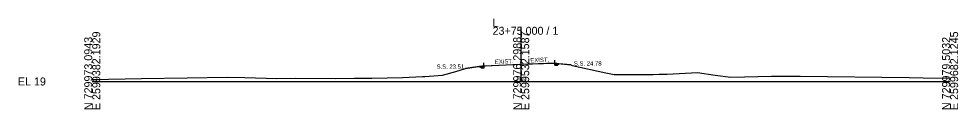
# Model space of a CAD drawing. Extents: x -26 to 3303, y -10 to 9555.
# Drawn here: x 1974.3 to 2302.8, y 7490.3 to 7521.9 of the extents above; entities that cross this region are included whole.
import ezdxf

# ---------------------------------------------------------------- set-up
doc = ezdxf.new("R2010")
doc.units = 0
for name, color, linetype in [('Exist Cross Section Cell', 7, 'Continuous'), ('Exist XS Center Line Elevation Label', 7, 'Continuous'), ('Exist XS Ground Line', 7, 'Continuous'), ('Prop XS Dump Level', 7, 'Continuous'), ('Prop XS Earthwork Shape', 7, 'Continuous'), ('Prop XS EOT Tick Mark', 7, 'Continuous'), ('Prop XS Finish Grade', 7, 'Continuous'), ('Prop XS Finish Grade Earthwork', 7, 'Continuous'), ('Prop XS Finish Grade Pavement', 7, 'Continuous'), ('Prop XS Pvmt Edge Slope', 7, 'Continuous'), ('Prop XS SE Text', 7, 'Continuous'), ('Prop XS SS Elevation Text', 7, 'Continuous'), ('Prop XS Subgrade Earthwork', 7, 'Continuous')]:
    doc.layers.add(name, color=color, linetype=linetype)

msp = doc.modelspace()

# ---------------------------------------------------------------- linework, layer by layer
at = {"layer": 'Exist Cross Section Cell'}
for p, q in [((2150, 7500), (2150, 7519.13)), ((2000, 7500), (2150, 7500)), ((2150, 7500), (2300, 7500))]:
    msp.add_line(p, q, dxfattribs=at)
at = {"layer": 'Exist XS Ground Line'}
msp.add_lwpolyline([(2000, 7500.64), (2017.24, 7501.01), (2033.2, 7501.24), (2047.35, 7501.51), (2053.4, 7501.41), (2064.5, 7501.05), (2071.22, 7501.13), (2085.17, 7501.1), (2091.57, 7501.12), (2097.78, 7501.22), (2108.45, 7501.45), (2115.5, 7501.73), (2115.89, 7501.74), (2116.29, 7501.76), (2122.44, 7502.19), (2127.19, 7503.49), (2130.51, 7504.51), (2134.28, 7505.07), (2136.97, 7505.47), (2139.8, 7505.62), (2149.5, 7506.01), (2150, 7506.03), (2161.78, 7506.38), (2167.39, 7505.78), (2167.87, 7505.63), (2179.59, 7502.97), (2182.53, 7502.42), (2185.23, 7502.4), (2192.01, 7502.5), (2196.18, 7502.39), (2198.21, 7502.57), (2201.05, 7502.59), (2211.67, 7503.13), (2217.87, 7502.24), (2223.3, 7501.5), (2237.58, 7501.91), (2240.49, 7501.9), (2247.55, 7501.91), (2285.74, 7501.36), (2290.59, 7501.3), (2300, 7501.15)], dxfattribs=at)
at = {"layer": 'Prop XS Dump Level'}
for p, q in [((2136.97, 7505.51), (2150, 7506.03)), ((2150, 7506.03), (2161.79, 7506.5))]:
    msp.add_line(p, q, dxfattribs=at)
at = {"layer": 'Prop XS Earthwork Shape'}
for points in [[(2135.47, 7505.28), (2130.51, 7504.51), (2134.28, 7505.07), (2135.49, 7505.25)], [(2134.28, 7505.07), (2135.49, 7505.25), (2135.47, 7505.28), (2130.51, 7504.51)], [(2136.1, 7504.64), (2135.49, 7505.25), (2136.97, 7505.47), (2136.97, 7504.67)], [(2136.97, 7504.67), (2136.1, 7504.64), (2135.49, 7505.25), (2136.97, 7505.47)], [(2161.78, 7506.38), (2163.12, 7506.23), (2162.59, 7505.7), (2161.78, 7505.67)], [(2162.59, 7505.7), (2163.12, 7506.23), (2161.78, 7506.38), (2161.78, 7505.67)], [(2163.12, 7506.23), (2163.21, 7506.32), (2167.39, 7505.78)], [(2163.21, 7506.32), (2167.39, 7505.78), (2163.12, 7506.23)]]:
    msp.add_lwpolyline(points, close=True, dxfattribs=at)
at = {"layer": 'Prop XS EOT Tick Mark'}
for p, q in [((2161.79, 7506.5), (2161.79, 7507.5)), ((2136.97, 7505.51), (2136.97, 7506.51))]:
    msp.add_line(p, q, dxfattribs=at)
at = {"layer": 'Prop XS Finish Grade'}
for p, q in [((2136.97, 7505.51), (2135.47, 7505.28)), ((2161.79, 7506.5), (2163.21, 7506.32))]:
    msp.add_line(p, q, dxfattribs=at)
at = {"layer": 'Prop XS Finish Grade Earthwork'}
for p, q in [((2135.47, 7505.28), (2130.51, 7504.51)), ((2163.21, 7506.32), (2167.39, 7505.78))]:
    msp.add_line(p, q, dxfattribs=at)
at = {"layer": 'Prop XS Finish Grade Pavement'}
for p, q in [((2136.97, 7505.51), (2150, 7506.03)), ((2150, 7506.03), (2161.79, 7506.5))]:
    msp.add_line(p, q, dxfattribs=at)
at = {"layer": 'Prop XS Pvmt Edge Slope'}
for p, q in [((2136.1, 7504.64), (2135.47, 7505.28)), ((2136.97, 7505.51), (2136.1, 7504.64)), ((2161.79, 7506.5), (2162.59, 7505.7)), ((2162.59, 7505.7), (2163.21, 7506.32))]:
    msp.add_line(p, q, dxfattribs=at)
at = {"layer": 'Prop XS Subgrade Earthwork'}
for p, q in [((2136.1, 7504.64), (2135.47, 7505.28)), ((2136.97, 7504.67), (2136.1, 7504.64)), ((2136.97, 7504.67), (2136.97, 7505.47)), ((2161.78, 7505.67), (2161.78, 7506.38)), ((2161.78, 7505.67), (2161.79, 7505.67)), ((2161.79, 7505.67), (2162.59, 7505.7)), ((2162.59, 7505.7), (2163.21, 7506.32))]:
    msp.add_line(p, q, dxfattribs=at)

# ---------------------------------------------------------------- texts
at = {"layer": 'Exist Cross Section Cell'}
for s, p in [('L', (2140, 7519.13)), ('23+75.000 / 1', (2140, 7516.33)), ('EL 19', (1974, 7498.6))]:
    msp.add_text(s, height=2.8, dxfattribs=at).set_placement(p)
for s, p in [('E 2599382.1929', (2002.8, 7490)), ('E 2599532.1587', (2152.8, 7490)), ('E 2599682.1245', (2302.8, 7490)), ('N 729973.0943', (2000, 7490)), ('N 729976.2988', (2150, 7490)), ('N 729979.5032', (2300, 7490))]:
    msp.add_text(s, height=2.8, rotation=90, dxfattribs=at).set_placement(p)
at = {"layer": 'Exist XS Center Line Elevation Label'}
msp.add_text('25.03', height=1, dxfattribs=at).set_placement((2148.27, 7500.53))
at = {"layer": 'Prop XS Dump Level'}
for p in [(2136.97, 7505.17), (2161.78, 7506.08)]:
    msp.add_text('Eop', height=0.3, dxfattribs=at).set_placement(p)
at = {"layer": 'Prop XS SE Text'}
for p in [(2140.83, 7506.16), (2153.24, 7506.66)]:
    msp.add_text('EXIST.', height=1.5, rotation=2.2906, dxfattribs=at).set_placement(p)
at = {"layer": 'Prop XS SS Elevation Text'}
for s, p in [('S.S. 24.78', (2168.44, 7505.57)), ('S.S. 23.51', (2120.42, 7504.46))]:
    msp.add_text(s, height=1.5, dxfattribs=at).set_placement(p)

doc.saveas('drawing.dxf')
